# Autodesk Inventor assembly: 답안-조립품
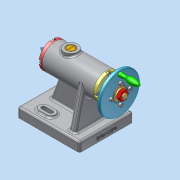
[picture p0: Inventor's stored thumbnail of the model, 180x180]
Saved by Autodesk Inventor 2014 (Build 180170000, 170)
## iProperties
Created: 2026-09
Part Number: 답안-조립품
Document SubType Name: Assembly
Designer: dg
Author: dg
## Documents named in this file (18)
- C:\Users\dg\Desktop\760903V1009\답안-조립품.iam
- C:\Users\dg\Desktop\760903V1009\본체.ipt
- C:\Users\dg\Desktop\760903V1009\가져온 구성요소\6각 구멍붙이 볼트 M3x8\6각 구멍붙이 볼트 M3x8.ipt
- C:\Users\dg\Desktop\760903V1009\가져온 구성요소\6각 너트 M8\6각 너트 M8.ipt
- C:\Users\dg\Desktop\760903V1009\가져온 구성요소\가이드 부시\가이드 부시.ipt
- C:\Users\dg\Desktop\760903V1009\가져온 구성요소\나사축\나사축.ipt
- C:\Users\dg\Desktop\760903V1009\가져온 구성요소\돌림판\돌림판.ipt
- C:\Users\dg\Desktop\760903V1009\가져온 구성요소\멈춤나사 M3\멈춤나사 M3.ipt
- C:\Users\dg\Desktop\760903V1009\가져온 구성요소\부시\부시.ipt
- C:\Users\dg\Desktop\760903V1009\가져온 구성요소\센터\센터.ipt
- C:\Users\dg\Desktop\760903V1009\가져온 구성요소\센터홀더\센터홀더.ipt
- C:\Users\dg\Desktop\760903V1009\가져온 구성요소\스톱퍼\스톱퍼.ipt
- C:\Users\dg\Desktop\760903V1009\가져온 구성요소\슬리브\슬리브.ipt
- C:\Users\dg\Desktop\760903V1009\가져온 구성요소\커버\커버.ipt
- C:\Users\dg\Desktop\760903V1009\가져온 구성요소\평 와셔 M8\평 와셔 M8.ipt
- C:\Users\dg\Desktop\760903V1009\가져온 구성요소\평행 키 4x4x10\평행 키 4x4x10.ipt
- C:\Users\dg\Desktop\760903V1009\가져온 구성요소\플랜지\플랜지.ipt
- C:\Users\dg\Desktop\760903V1009\가져온 구성요소\핸들\핸들.ipt
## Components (16 placed, 5 different names)
1. 6각 너트 M8:1
2. 가이드 부시:1
3. 플랜지:1
4. 핸들:1
5. 6각 구멍붙이 볼트 M3x8:2
6. 6각 구멍붙이 볼트 M3x8:3
7. 6각 구멍붙이 볼트 M3x8:4
8. 6각 구멍붙이 볼트 M3x8:5
9. 6각 구멍붙이 볼트 M3x8:1
10. 6각 구멍붙이 볼트 M3x8:6
11. 6각 구멍붙이 볼트 M3x8:7
12. 6각 구멍붙이 볼트 M3x8:8
13. 6각 구멍붙이 볼트 M3x8:9
14. 6각 구멍붙이 볼트 M3x8:10
15. 6각 구멍붙이 볼트 M3x8:11
16. 6각 구멍붙이 볼트 M3x8:12
